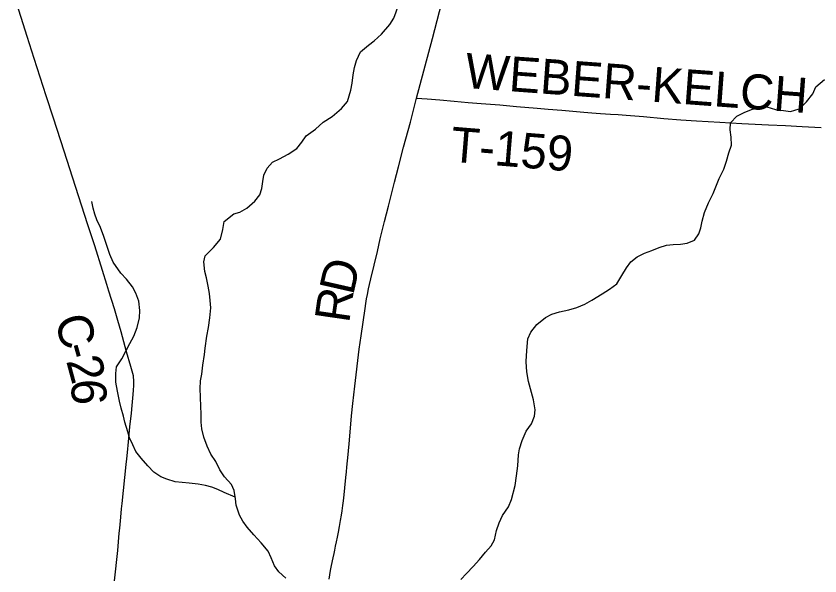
# Model space of a CAD drawing. Extents: x 1451455 to 1749751, y 218250 to 574981.
# Drawn here: x 1589405 to 1596296, y 345060 to 349860 of the extents above; entities that cross this region are included whole.
import ezdxf

# ---------------------------------------------------------------- set-up
doc = ezdxf.new("R2010")
doc.units = 0
for name, color, linetype in [('GM_X_County_Road', 7, 'Continuous'), ('GM_X_County_Road_Text', 7, 'Continuous'), ('GM_X_Minor_River', 7, 'Continuous'), ('GM_X_Township_Road', 7, 'Continuous'), ('GM_X_Township_Road_Text', 7, 'Continuous')]:
    doc.layers.add(name, color=color, linetype=linetype)

msp = doc.modelspace()

# ---------------------------------------------------------------- linework, layer by layer
at = {"layer": 'GM_X_County_Road'}
for points in [[(1592838.5, 349155.8), (1592973.9, 349668.3), (1593055.9, 349975.9), (1593099.4, 350147.6), (1593120.5, 350240.1), (1593127.6, 350275.1), (1593133.3, 350307.6), (1593138.4, 350339.3), (1593142.6, 350369.1), (1593146.2, 350400.5), (1593149.6, 350430.8), (1593152.3, 350467.3), (1593156.5, 350522.3), (1593159.2, 350560.2), (1593161.8, 350607.3), (1593163.6, 350659.6), (1593165.5, 350728.5), (1593166.2, 350775.9), (1593166.6, 350820.2), (1593167.2, 350859.8), (1593168.4, 350886.2), (1593169.4, 350904.3)], [(1590250.4, 345018.4), (1590276.5, 345278.1), (1590290.1, 345427.8), (1590294, 345469.3), (1590302.8, 345565), (1590309.8, 345633.8), (1590314.8, 345682.3), (1590326.2, 345793.3), (1590349.7, 346015), (1590354.8, 346063.9), (1590360.3, 346119.4), (1590369.1, 346210.8), (1590381.8, 346338.4), (1590393.4, 346454.7), (1590400, 346520.7), (1590409.1, 346615.4), (1590411.5, 346651.3), (1590413.9, 346693.2), (1590415.5, 346718.6), (1590415.1, 346742.9), (1590413.3, 346757.6), (1590410.9, 346774.3), (1590406.3, 346795.8), (1590400.9, 346815.3), (1590389.4, 346856.6), (1590353.3, 346981.4), (1590304.8, 347154), (1590277.5, 347250.8), (1590248.7, 347350.4), (1590201.8, 347502.6), (1590184.2, 347558.5), (1590146.6, 347677.8), (1590079.7, 347890.1), (1590019.6, 348070.7), (1589914.6, 348398.7), (1589817.5, 348701.7), (1589726.4, 348986), (1589663.8, 349176.1), (1589561.3, 349496.3), (1589501.1, 349684.4), (1589448.8, 349847.9), (1589405.4, 349982.9)], [(1592088.5, 345033.3), (1592094.1, 345068.5), (1592100.7, 345106.2), (1592109.3, 345148.8), (1592123.3, 345215.3), (1592131, 345251.2), (1592137, 345279.4), (1592144.9, 345315.5), (1592152.9, 345353.1), (1592161, 345392.7), (1592169.9, 345436.4), (1592178.3, 345483.4), (1592187.2, 345536.4), (1592194.4, 345581.5), (1592200.1, 345617.9), (1592206.1, 345662.7), (1592211.3, 345702.6), (1592217.1, 345753.9), (1592223.9, 345814.1), (1592233.5, 345904.4), (1592237.8, 345951.7), (1592241.3, 345993.8), (1592246.1, 346046.4), (1592250.8, 346099.7), (1592262.6, 346225.2), (1592281.6, 346431.8), (1592291.6, 346538.5), (1592309.4, 346688.3), (1592347.6, 347003.3), (1592362.7, 347117.3), (1592397, 347354.3), (1592403.2, 347395.7), (1592409.7, 347435.2), (1592417.1, 347472.6), (1592427, 347521.2), (1592435.7, 347559.3), (1592447, 347606.2), (1592502.7, 347841.8), (1592527.3, 347950.8), (1592564.2, 348098), (1592599, 348230.4), (1592649.7, 348434.8), (1592684.8, 348567.3), (1592727.4, 348736.4), (1592785.6, 348951.7), (1592838.5, 349155.8)]]:
    msp.add_lwpolyline(points, dxfattribs=at)
at = {"layer": 'GM_X_Minor_River'}
for points in [[(1591971.7, 348891.9), (1592036.4, 348951.1), (1592115, 349000), (1592195.9, 349068.9), (1592246.7, 349128.2), (1592276, 349224), (1592286.9, 349284), (1592295.9, 349356), (1592306.8, 349418), (1592323.7, 349479.8), (1592356.7, 349553.5), (1592425.5, 349610.6), (1592475.9, 349647.9), (1592538.7, 349705), (1592609.7, 349788.1), (1592642.5, 349843.7), (1592663.3, 349897.5), (1592682, 349951.4)], [(1596234.6, 349194.4), (1596261.4, 349254.1), (1596336.2, 349317)], [(1593216.5, 345028.1), (1593267.2, 345079.5), (1593324.1, 345140.8), (1593378.9, 345200.1), (1593429.7, 345263.5), (1593478.4, 345316.8), (1593507.2, 345370.5), (1593524.3, 345448.4), (1593545.3, 345514.3), (1593576.2, 345577.9), (1593625.2, 345651.3), (1593652.1, 345715.1), (1593683.8, 345834.9), (1593695, 345916.9), (1593706.2, 346002.9), (1593711.6, 346099), (1593720.4, 346151), (1593743.4, 346220.8), (1593778.5, 346300.4), (1593823.4, 346363.9), (1593850.3, 346429.6), (1593855.1, 346483.6), (1593840.4, 346570.1), (1593815.8, 346664.6), (1593796.8, 346727.1), (1593784, 346809.4), (1593779.3, 346895.7), (1593780.1, 346949.8), (1593785.2, 347025.9), (1593792.2, 347093.9), (1593817, 347149.7), (1593869.8, 347215), (1593944.6, 347276), (1593996.9, 347305.2), (1594063.1, 347324.3), (1594143.2, 347341.1), (1594211.4, 347362.1), (1594279.7, 347389.1), (1594342.1, 347424.2), (1594428.8, 347479), (1594493.3, 347518.1), (1594553.9, 347565.2), (1594598.8, 347634.7), (1594637.7, 347700.2), (1594676.4, 347753.7), (1594729, 347797), (1594793.3, 347828.1), (1594855.5, 347849.2), (1594917.8, 347876.3), (1594982, 347895.3), (1595038, 347902.5), (1595099.9, 347905.5), (1595157.9, 347912.6), (1595220.2, 347937.7), (1595256.9, 347993.3), (1595275.7, 348045.1), (1595286.5, 348103), (1595307.5, 348176.9), (1595340.6, 348258.5), (1595381.7, 348338), (1595433.5, 348467.5), (1595472.6, 348549), (1595495.5, 348614.8), (1595516.5, 348686.6), (1595537.5, 348754.4), (1595536.4, 348820.6), (1595527.4, 348884.8), (1595530.2, 348944.9), (1595585, 349002.2), (1595651.4, 349037.2), (1595717.6, 349062.2), (1595781.7, 349079.2), (1595839.7, 349082.3), (1595915.2, 349059.1), (1595983, 349050), (1596044.8, 349043.1), (1596116.9, 349064), (1596179.7, 349125.1), (1596234.6, 349194.4)], [(1591716.7, 345040.6), (1591657.6, 345095.7), (1591620.4, 345146.3), (1591591.5, 345214.9), (1591566.4, 345273.4), (1591505.5, 345342.5), (1591442.7, 345413.6), (1591385.7, 345478.6), (1591348.5, 345529.3), (1591319.4, 345581.9), (1591292.7, 345666.5), (1591287.5, 345720.7), (1591274.6, 345793.1), (1591251.4, 345843.5), (1591192.5, 345910.6), (1591153.4, 345969.3), (1591116.5, 346042), (1591073.5, 346104.8), (1591042.6, 346171.5), (1591013.8, 346250.1), (1590996.9, 346320.5), (1590991.8, 346378.8), (1590992.9, 346452.9), (1590989.7, 346511.1), (1590985, 346595.4), (1590982, 346663.6), (1590987, 346731.7), (1590997.9, 346789.7), (1591007, 346865.7), (1591020.4, 346957.7), (1591027.2, 347013.8), (1591040.7, 347115.8), (1591055.8, 347189.8), (1591067, 347271.8), (1591074.3, 347359.9), (1591069.3, 347422.1), (1591062.1, 347480.4), (1591051.1, 347544.7), (1591038.2, 347615.1), (1591023, 347669.5), (1591014.3, 347751.8), (1591025, 347805.8), (1591098, 347876.8), (1591156.9, 347946.1), (1591178.2, 348030), (1591189.2, 348100), (1591272, 348164.9), (1591322.1, 348178.1), (1591382.6, 348213.3), (1591451.3, 348272.4), (1591494.1, 348327.9), (1591510.9, 348381.8), (1591519.7, 348441.8), (1591530.5, 348495.7), (1591557.4, 348557.5), (1591602.1, 348608.9), (1591662.4, 348636), (1591738.8, 348675), (1591811.5, 348726), (1591854.2, 348779.5), (1591890.9, 348833), (1591971.7, 348891.9)], [(1591284.8, 345736), (1591188.4, 345774.3), (1591134.9, 345801.2), (1591083.3, 345820), (1591029.6, 345834.8), (1590965.8, 345845.8), (1590890, 345855), (1590830.2, 345859.9), (1590770.4, 345866.8), (1590698.8, 345889.9), (1590647.2, 345910.8), (1590585.9, 345949.8), (1590534.8, 346002.7), (1590477.8, 346069.7), (1590430.8, 346126.5), (1590405.6, 346183.1), (1590378.6, 346243.6), (1590363.4, 346294), (1590338.7, 346378.6), (1590325.5, 346430.9), (1590306.5, 346497.3), (1590291.4, 346557.7), (1590274.8, 346644.2), (1590261.9, 346720.6), (1590261.1, 346796.8), (1590265.9, 346852.8), (1590312.9, 346920.3), (1590347.9, 346994), (1590380.7, 347051.6), (1590415.6, 347115.3), (1590442.7, 347189), (1590463.9, 347272.9), (1590466.9, 347337), (1590458.1, 347415.4), (1590431.1, 347484), (1590402, 347538.5), (1590351.1, 347605.5), (1590303.9, 347656.3), (1590237.4, 347749.5), (1590210.4, 347816.1), (1590181.8, 347902.8), (1590158.8, 347969.3), (1590128, 348048), (1590097, 348112.6), (1590081.8, 348162.9), (1590066.6, 348213.3), (1590053.5, 348269.6)]]:
    msp.add_lwpolyline(points, dxfattribs=at)
at = {"layer": 'GM_X_Township_Road'}
msp.add_lwpolyline([(1592838.5, 349155.8), (1592930.7, 349149.5), (1593037, 349141.2), (1593161.6, 349129.9), (1593281.8, 349119.9), (1593392.5, 349111.7), (1593550.9, 349098.3), (1593695.9, 349086.1), (1593871.3, 349070.9), (1593967.6, 349062.7), (1594084.8, 349053.1), (1594271, 349036.2), (1594341.3, 349029.7), (1594415.1, 349023.6), (1594499.7, 349018.8), (1594565.5, 349015.4), (1594634.1, 349010.7), (1594782.7, 348998), (1594958.9, 348983.2), (1595102.6, 348971.9), (1595236.7, 348962), (1595439.4, 348951.1), (1595626.9, 348938.9), (1595856.5, 348926.8), (1596001.9, 348920.7), (1596143.4, 348912.9), (1596305.7, 348904.2)], dxfattribs=at)

# ---------------------------------------------------------------- texts
at = {"layer": 'GM_X_County_Road_Text'}
for s, rotation, p in [('D', 77.18394, (1592294.3, 347459.3)), ('R', 81.71645, (1592260, 347221.6)), ('C', 285.71005, (1589733.4, 347260)), ('-', 285.61729, (1589800, 347022.9)), ('2', 285.17982, (1589833.1, 346904.9)), ('6', 271.11893, (1589878.7, 346745.7))]:
    msp.add_text(s, height=300, rotation=rotation, dxfattribs=at).set_placement(p)
at = {"layer": 'GM_X_Township_Road_Text'}
for s, rotation, p in [('WEBER-KELCH', 355.77954, (1593246.4, 349245.2)), ('T-159', 355.28245, (1593122.2, 348613.1))]:
    msp.add_text(s, height=300, rotation=rotation, dxfattribs=at).set_placement(p)

doc.saveas('drawing.dxf')
